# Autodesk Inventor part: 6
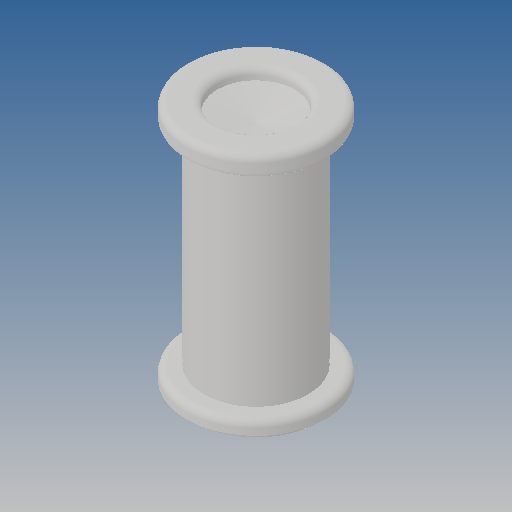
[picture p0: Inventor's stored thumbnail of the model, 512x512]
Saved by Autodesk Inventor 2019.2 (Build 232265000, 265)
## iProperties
Created: 2012-09
Part Number: 6
Material: Ogólny
Document SubType Name: Modeling
Designer: CADENGINEERING4
Density: 1 g/cm^3
Appearance: Domyślna
Author: CADENGINEERING4
Revision Number: ÈÎºÎ
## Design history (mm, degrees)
feature "Ðý×ª1"
node "Bryła1"
